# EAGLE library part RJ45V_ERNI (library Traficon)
CT: 12-06-08 Changed the tPlace layer with conformance to the HALO HFJV1-2450 component.
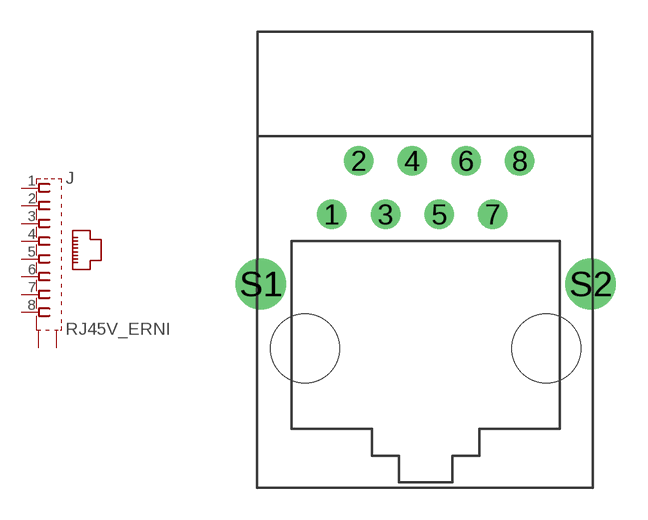
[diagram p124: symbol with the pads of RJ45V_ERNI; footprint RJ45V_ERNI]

Designator prefix J

## RJ45V_ERNI  [RJ45V_ERNI]
1  1  pas
2  2  pas
3  3  pas
4  4  pas
5  5  pas
6  6  pas
7  7  pas
8  8  pas
S1  S1  pas
S2  S2  pas

## Footprint RJ45V_ERNI (pad centres in mm)
drill 0.889 round: 1 -4.445,6.35; 2 -3.175,8.89; 3 -1.905,6.35; 4 -0.635,8.89; 5 0.635,6.35; 6 1.905,8.89; 7 3.175,6.35; 8 4.445,8.89
drill 1.6 round: S1 -7.81,3.05; S2 7.81,3.05
hole 3.251 at -5.715,0
hole 3.251 at 5.715,0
